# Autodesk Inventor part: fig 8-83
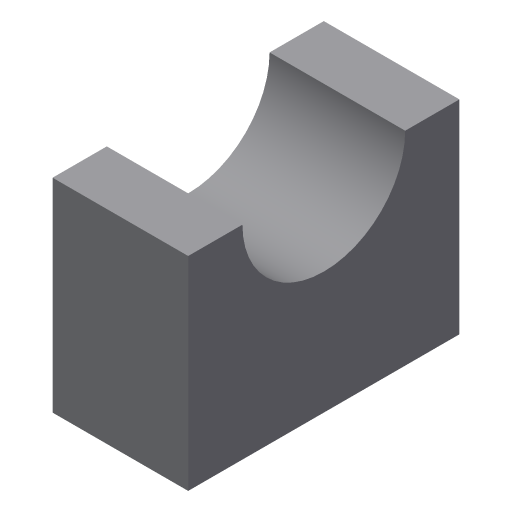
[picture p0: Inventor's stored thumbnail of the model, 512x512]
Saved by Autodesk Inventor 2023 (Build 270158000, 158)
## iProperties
Created: 2002-01
Part Number: fig 8-83
Document SubType Name: Modeling
Designer: ***
Density: 1 g/cm^3
Material: Generic
Appearance: Default
Control State: 0
Master: False
Checked Out: False
Shininess: 77.0
Length Units: 11269
Angle Units: 11279
Time Units: 11290
Mass Units: 11283
Length Display Precision: 3
Angle Display Precision: 2
Density: 0.0
Volumn: 0.0
Area: 0.0
PropertySet Name: Model Information
Author: ***
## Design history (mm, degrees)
sketch "Sketch5"
  geometry: L1 (-22.226, 10.275)-(-14.226, 10.275); L2 (9.774, 10.275)-(17.774, 10.275); L3 (17.774, 10.275)-(17.774, -19.725); L4 (17.774, -19.725)-(-22.226, -19.725); L5 (-22.226, -19.725)-(-22.226, 10.275); A1 r 12 centre (-2.226, 10.275) between (-14.226, 10.275) and (9.774, 10.275)
  constraints: 10 end point, 2 equal length, 2 parallel, 2 point on circle, 1 centre point, 1 collinear, 1 horizontal, 1 perpendicular, 1 point on line
  dimensions: "d7" = 40 distance of L3.end L4.end; "d8" = 30 distance of L2.end L3.end; "d9" = 12 radius of A1
extrude "Extrusion2" new body sketch "Sketch5" distance "d10" = 20; taper "d11" = 0 deg
workplane "Work Plane3"
sketch "Sketch6"
  geometry: L1 (19.321, -18.091)-(12.314, -18.091); L2 (12.314, -18.091)-(12.314, -11.217); L3 (12.314, -11.217)-(7.026, -11.217); L4 (7.026, -11.217)-(7.026, 7.425); L5 (7.026, 7.425)-(7.026, 14.035); L6 (7.026, 14.035)-(-10.029, 14.035)
  constraints: 12 end point, 4 parallel, 1 horizontal, 1 perpendicular
split "Split5" sketch "Sketch6"
body "Solid1"
other parameters: "d12" = 15
